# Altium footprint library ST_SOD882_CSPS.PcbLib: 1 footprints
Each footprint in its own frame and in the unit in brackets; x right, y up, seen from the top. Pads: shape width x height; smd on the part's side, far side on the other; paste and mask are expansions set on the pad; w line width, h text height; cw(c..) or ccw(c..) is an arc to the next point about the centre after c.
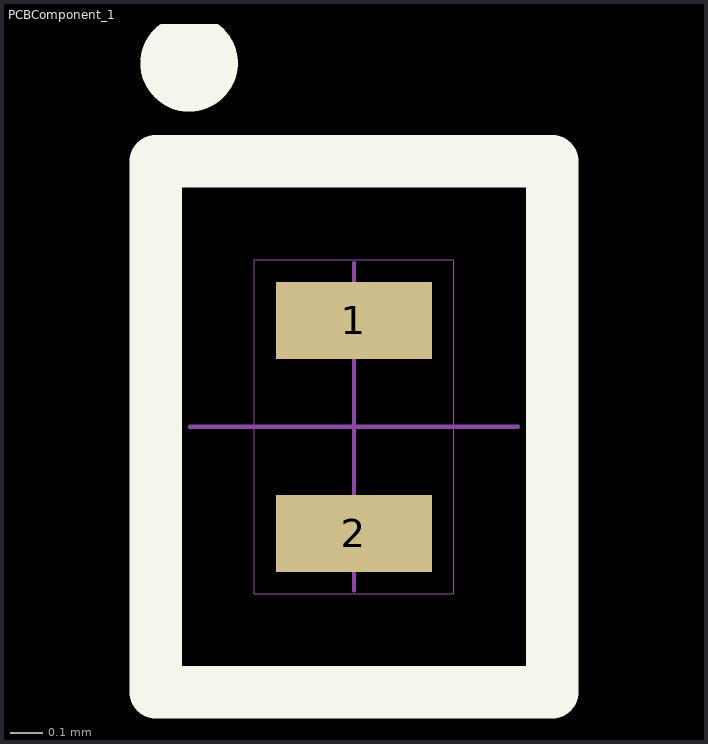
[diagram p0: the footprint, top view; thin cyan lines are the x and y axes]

## PCBComponent_1 [mm]
pads (2):
  rect 0.475x0.235 smd paste-2539.97 mask+0.05: 1(-1269.282,-1264.968) 2(-1269.282,-1265.618)
Top Overlay:
  circle w0.254: c-1269.786,-1264.183 r0.022
  lines w0.16: -1269.887,-1266.103 -1268.677,-1266.103 -1268.677,-1264.483 -1269.887,-1264.483 -1269.887,-1266.103
Top Paste:
  region: -1269.06,-1265.509 -1269.06,-1265.714 -1269.505,-1265.714 -1269.505,-1265.509
  region: -1269.505,-1265.078 -1269.505,-1264.873 -1269.06,-1264.873 -1269.06,-1265.078
Mechanical 1:
  lines w0: -1269.587,-1265.803 -1268.977,-1265.803 -1268.977,-1264.783 -1269.587,-1264.783 -1269.587,-1265.803
  lines w0.013: -1269.782,-1265.293 -1268.782,-1265.293 ; -1269.282,-1265.793 -1269.282,-1264.793
3D body: height 0.31, standoff 0.01, extent -1269.587,-1265.803 -1268.977,-1264.783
